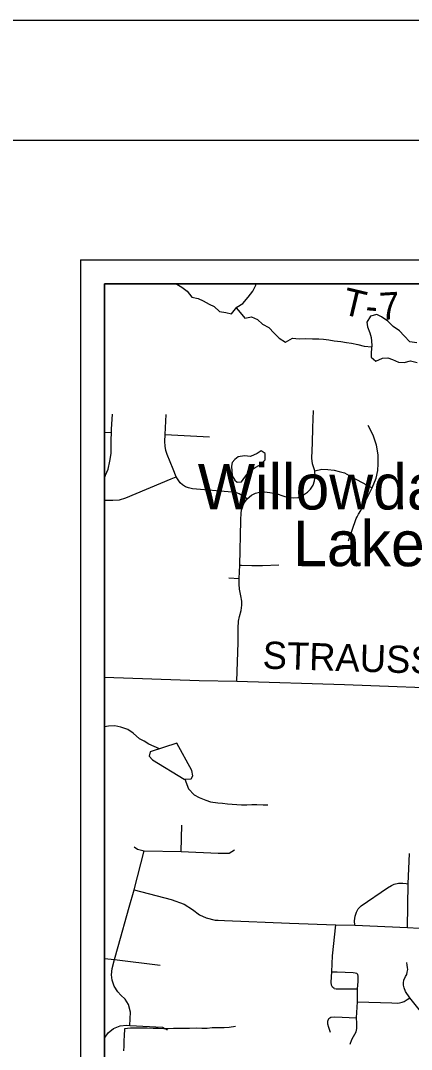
# Model space of a CAD drawing. Extents: x 25.6 to 80.6, y 0.2 to 24.5.
# Drawn here: x 37.263 to 38.894, y 17.932 to 22.23 of the extents above; entities that cross this region are included whole.
import ezdxf

# ---------------------------------------------------------------- set-up
doc = ezdxf.new("R2010")
doc.units = 0
for name, color, linetype in [('GM_X_County_Road', 7, 'Continuous'), ('GM_X_County_Road_Text', 7, 'Continuous'), ('GM_X_Minor_Lake', 7, 'Continuous'), ('GM_X_Minor_Lake_Text', 7, 'Continuous'), ('GM_X_Minor_River', 7, 'Continuous'), ('GM_X_Township_Road', 7, 'Continuous'), ('GM_X_Township_Road_Text', 7, 'Continuous'), ('SH_Border', 7, 'Continuous'), ('SH_Cut_Line', 7, 'Continuous'), ('SH_Data', 7, 'Continuous'), ('SH_Text', 7, 'Continuous')]:
    doc.layers.add(name, color=color, linetype=linetype)

msp = doc.modelspace()

# ---------------------------------------------------------------- linework, layer by layer
at = {"layer": 'GM_X_County_Road'}
msp.add_lwpolyline([(37.6128, 19.4872), (38.0081, 19.473), (38.1648, 19.4698), (38.614, 19.4559), (39.1271, 19.4367), (39.3128, 19.4303)], dxfattribs=at)
at = {"layer": 'GM_X_Minor_Lake'}
for points in [[(38.9165, 20.8834), (38.8877, 20.8884), (38.8631, 20.9124), (38.8439, 20.9342), (38.8179, 20.9514), (38.7956, 20.9747), (38.7689, 20.9926), (38.7498, 21.0022), (38.7233, 20.9958), (38.707, 20.9706), (38.7102, 20.9509), (38.7196, 20.9252), (38.7252, 20.9055), (38.7286, 20.8736), (38.7259, 20.8432), (38.7254, 20.8242), (38.7453, 20.807), (38.7732, 20.8202), (38.7952, 20.8213), (38.8142, 20.8147), (38.8394, 20.8028), (38.8637, 20.8023), (38.8894, 20.8087), (38.9175, 20.8022)], [(38.9165, 20.8834), (38.8877, 20.8884), (38.8631, 20.9124), (38.8439, 20.9342), (38.8179, 20.9514), (38.7956, 20.9747), (38.7689, 20.9926), (38.7498, 21.0022), (38.7233, 20.9958), (38.707, 20.9706), (38.7102, 20.9509), (38.7196, 20.9252), (38.7252, 20.9055), (38.7286, 20.8736), (38.7259, 20.8432), (38.7254, 20.8242), (38.7453, 20.807), (38.7732, 20.8202), (38.7952, 20.8213), (38.8142, 20.8147), (38.8394, 20.8028), (38.8637, 20.8023), (38.8894, 20.8087), (38.9175, 20.8022)], [(38.1452, 20.3285), (38.1561, 20.3096), (38.166, 20.3021), (38.1842, 20.3024), (38.1992, 20.3223), (38.2163, 20.346), (38.2419, 20.363), (38.26, 20.3723), (38.2832, 20.3946), (38.2829, 20.422), (38.2668, 20.4332), (38.2495, 20.4208), (38.2224, 20.4083), (38.1973, 20.4119), (38.1708, 20.407), (38.1573, 20.397), (38.1461, 20.3832), (38.1425, 20.3687)], [(38.1425, 20.3687), (38.1452, 20.3285)], [(37.9146, 19.2118), (37.8036, 19.1756), (37.7992, 19.1566), (37.8131, 19.1416), (37.946, 19.0603), (37.9748, 19.0622), (37.9815, 19.0752), (37.9774, 19.0964)], [(37.9774, 19.0964), (37.9146, 19.2118)]]:
    msp.add_lwpolyline(points, dxfattribs=at)
at = {"layer": 'GM_X_Minor_River'}
for points in [[(37.9128, 21.1303), (37.9149, 21.1284), (37.9355, 21.1165), (37.9585, 21.0993), (37.9777, 21.0752), (38.0036, 21.0695), (38.0242, 21.0591), (38.0494, 21.0449), (38.0699, 21.0361), (38.0922, 21.0151), (38.1188, 21.0108), (38.1423, 21.005), (38.1648, 21.0326), (38.1896, 21.0481), (38.212, 21.0742), (38.2322, 21.1002), (38.244, 21.1247), (38.2452, 21.1303)], [(38.1628, 21.0302), (38.1787, 21.01), (38.1987, 20.9867), (38.2267, 20.9931), (38.2511, 20.9812), (38.2718, 20.9617), (38.2993, 20.9484), (38.3215, 20.9236), (38.3415, 20.9033), (38.3682, 20.8869), (38.3969, 20.9032), (38.4257, 20.9005), (38.453, 20.9023), (38.4811, 20.9011), (38.5069, 20.8999), (38.5273, 20.8986), (38.5494, 20.8959), (38.5714, 20.8916), (38.5995, 20.8888), (38.6223, 20.8853), (38.6436, 20.8825), (38.6694, 20.8775), (38.696, 20.8702), (38.728, 20.867)], [(37.8418, 19.1881), (37.7986, 19.2074), (37.7788, 19.2194), (37.7589, 19.229), (37.7321, 19.253), (37.7099, 19.2687), (37.6817, 19.2782), (37.6567, 19.284), (37.6294, 19.2822), (37.6128, 19.28)], [(37.9475, 19.0604), (37.9639, 19.0203), (37.987, 18.9955), (38.0083, 18.9844), (38.0358, 18.9725), (38.0548, 18.9659), (38.0852, 18.9617), (38.1057, 18.9604), (38.1262, 18.9576), (38.1459, 18.9556), (38.1657, 18.9543), (38.1846, 18.9538), (38.2066, 18.9533), (38.2271, 18.955), (38.2483, 18.9545), (38.2749, 18.9533), (38.2938, 18.9528)], [(38.1595, 18.0271), (38.133, 18.023), (38.1125, 18.022), (38.0845, 18.0224), (38.0617, 18.0214), (38.0413, 18.0189), (38.0185, 18.0186), (37.9988, 18.0199), (37.967, 18.0188), (37.9465, 18.0193), (37.901, 18.0188), (37.879, 18.0177), (37.8601, 18.0175), (37.8365, 18.0188), (37.8153, 18.0185), (37.791, 18.0198), (37.7652, 18.0202), (37.7213, 18.0197), (37.6963, 18.0171), (37.6943, 17.989), (37.6938, 17.9685), (37.6941, 17.9457), (37.6928, 17.9252)]]:
    msp.add_lwpolyline(points, dxfattribs=at)
at = {"layer": 'GM_X_Township_Road'}
for p, q in [((37.6128, 20.5104), (37.6423, 20.5093)), ((37.8663, 20.5003), (38.0505, 20.4916)), ((38.1311, 19.9013), (38.1747, 19.899)), ((37.9328, 18.7581), (37.9352, 18.8679))]:
    msp.add_line(p, q, dxfattribs=at)
for points in [[(38.2076, 20.2323), (38.2262, 20.247), (38.2435, 20.2561), (38.2595, 20.2599), (38.2812, 20.2617), (38.3033, 20.2587), (38.3336, 20.253), (38.3569, 20.2448), (38.379, 20.2379), (38.4011, 20.2361), (38.4205, 20.2379), (38.4392, 20.2461), (38.4599, 20.2595), (38.472, 20.2721), (38.4833, 20.2889), (38.4889, 20.3071), (38.4915, 20.3249), (38.4902, 20.3495), (38.4811, 20.3777), (38.4777, 20.4015), (38.4807, 20.4664), (38.4829, 20.5287), (38.4846, 20.6005)], [(37.6423, 20.5093), (37.6428, 20.5226), (37.6468, 20.5854)], [(37.9151, 20.3195), (37.9118, 20.3246), (37.8988, 20.3559), (37.8743, 20.4167), (37.8687, 20.4346), (37.8657, 20.4524), (37.8651, 20.472), (37.8663, 20.5003), (37.87, 20.5839)], [(37.6128, 20.3182), (37.6174, 20.3313), (37.6276, 20.3563), (37.6352, 20.3896), (37.6403, 20.4221), (37.6413, 20.4772), (37.6423, 20.5093)], [(38.6314, 20.0561), (38.6631, 20.1501), (38.6669, 20.1574), (38.6701, 20.1626), (38.6735, 20.1681), (38.6828, 20.1838), (38.73, 20.2781), (38.7464, 20.3188), (38.7529, 20.35), (38.7555, 20.3777), (38.7551, 20.4153), (38.7482, 20.4556), (38.7352, 20.4937), (38.7257, 20.5149), (38.7131, 20.5382)], [(38.4902, 20.3495), (38.5205, 20.3556), (38.5448, 20.3552), (38.5707, 20.3517), (38.5924, 20.3469), (38.6144, 20.34), (38.6443, 20.324), (38.73, 20.2781)], [(37.6128, 20.2262), (37.6474, 20.2262), (37.6754, 20.2285), (37.7025, 20.2361), (37.8906, 20.3158), (37.9118, 20.3246)], [(38.2076, 20.2323), (38.1752, 20.253), (38.1609, 20.2582), (38.1453, 20.2595), (37.9806, 20.2742), (37.964, 20.2773), (37.9511, 20.2828), (37.9382, 20.2902), (37.9284, 20.2994), (37.9151, 20.3195)], [(38.1648, 19.4698), (38.17, 19.6324), (38.1704, 19.6917), (38.1717, 19.7211), (38.176, 19.741), (38.1834, 19.7661), (38.1864, 19.7874), (38.1855, 19.8042), (38.1821, 19.8272), (38.1756, 19.8544), (38.1747, 19.8748), (38.1747, 19.899), (38.1778, 19.9553), (38.1825, 20.1409), (38.1834, 20.1751), (38.1864, 20.1907), (38.1903, 20.2033), (38.1977, 20.2167), (38.2076, 20.2323)], [(38.1778, 19.9553), (38.1848, 19.9551), (38.2284, 19.954), (38.2717, 19.9535), (38.3409, 19.9561)], [(37.7188, 18.0322), (37.7214, 18.0875), (37.7129, 18.1197), (37.6991, 18.142), (37.6813, 18.1585), (37.6682, 18.1723), (37.6537, 18.1963), (37.6455, 18.2213), (37.6422, 18.243), (37.6451, 18.269), (37.6553, 18.3068), (37.6705, 18.362), (37.7155, 18.5261), (37.7361, 18.5978), (37.7788, 18.7613)], [(37.7361, 18.7787), (37.7511, 18.7684), (37.7788, 18.7613), (37.9328, 18.7581), (38.0876, 18.751), (38.1326, 18.7518), (38.1555, 18.7653)], [(38.8779, 18.4416), (38.8805, 18.6236), (38.886, 18.7505)], [(38.6581, 18.4508), (38.6559, 18.4692), (38.6594, 18.4883), (38.6644, 18.5048), (38.6715, 18.5183), (38.684, 18.5319), (38.7933, 18.6061), (38.8108, 18.6166), (38.8219, 18.6216), (38.8404, 18.6256), (38.8575, 18.6266), (38.8715, 18.6246), (38.8805, 18.6236)], [(37.7361, 18.5978), (37.8917, 18.5575), (37.9455, 18.5378), (37.9802, 18.5157), (38.0094, 18.4936), (38.0378, 18.4809), (38.075, 18.4722), (38.0872, 18.4715)], [(38.0872, 18.4715), (38.1137, 18.4699), (38.3845, 18.4588), (38.5779, 18.4524), (38.6581, 18.4508), (38.8779, 18.4416), (39.1211, 18.4267)], [(38.5713, 18.1862), (38.5638, 18.1922), (38.56, 18.2), (38.5592, 18.212), (38.5622, 18.2555), (38.5638, 18.3219), (38.5779, 18.4524)], [(37.6128, 18.311), (37.6553, 18.3068), (37.8457, 18.2834)], [(39.1098, 18.0552), (39.0148, 18.0575), (38.9845, 18.0586), (38.9645, 18.0634), (38.9504, 18.071), (38.932, 18.0916), (38.8872, 18.1478), (38.8696, 18.174), (38.8631, 18.1892), (38.8603, 18.2), (38.8603, 18.2092), (38.8625, 18.2206), (38.869, 18.2363), (38.8739, 18.2444), (38.8766, 18.2547), (38.8782, 18.265), (38.8777, 18.2742), (38.8766, 18.2834), (38.8744, 18.2954)], [(38.5622, 18.2555), (38.5836, 18.2564), (38.651, 18.2528), (38.6583, 18.252), (38.664, 18.2499), (38.6694, 18.245)], [(38.6386, 17.9536), (38.6457, 17.9725), (38.6522, 17.986), (38.6625, 18.0055), (38.6657, 18.0191), (38.6657, 18.0412), (38.6646, 18.0633), (38.6686, 18.1307), (38.6683, 18.1849), (38.6711, 18.216), (38.6719, 18.2293), (38.6719, 18.2379), (38.6694, 18.245)], [(38.5713, 18.1862), (38.5803, 18.1843), (38.6228, 18.1851), (38.6451, 18.1854), (38.6683, 18.1849)], [(38.6686, 18.1307), (38.8121, 18.1258), (38.8341, 18.125), (38.8446, 18.1258), (38.8547, 18.1285), (38.8628, 18.1318), (38.8766, 18.1396), (38.8872, 18.1478)], [(38.5564, 18.0028), (38.5488, 18.0228), (38.5455, 18.0364), (38.5455, 18.0499), (38.5488, 18.0602), (38.5575, 18.0667), (38.5742, 18.0678), (38.6646, 18.0633)], [(37.6128, 17.9779), (37.6129, 17.9783), (37.6287, 18.0013), (37.6498, 18.0184), (37.678, 18.0296), (37.705, 18.0329), (37.7188, 18.0322), (37.8556, 18.0243), (37.8747, 18.0132)]]:
    msp.add_lwpolyline(points, dxfattribs=at)
at = {"layer": 'SH_Border'}
msp.add_lwpolyline([(37.0128, 21.7303), (69.0128, 21.7303), (69.0128, 0.7303), (37.0128, 0.7303)], close=True, dxfattribs=at)
at = {"layer": 'SH_Cut_Line'}
msp.add_lwpolyline([(35.5128, 0.2303), (69.5128, 0.2303), (69.5128, 22.2303), (35.5128, 22.2303)], close=True, dxfattribs=at)
at = {"layer": 'SH_Data'}
for p, q in [((37.5128, 21.2303), (44.5128, 21.2303)), ((37.5128, 21.2303), (37.5128, 14.2303)), ((37.6128, 21.1303), (37.6128, 14.3303)), ((37.6128, 21.1303), (44.4128, 21.1303)), ((37.6128, 21.1303), (37.6128, 14.3303)), ((37.6128, 21.1303), (44.4128, 21.1303))]:
    msp.add_line(p, q, dxfattribs=at)
at = {"layer": 'SH_Text'}
for points in [[(37.6128, 21.1303), (44.4128, 21.1303), (44.4128, 14.3303), (37.6128, 14.3303)], [(37.6128, 21.1303), (44.4128, 21.1303), (44.4128, 14.3303), (37.6128, 14.3303)], [(37.6128, 17.7303), (41.0128, 17.7303), (41.0128, 21.1303), (37.6128, 21.1303)], [(37.6128, 17.7303), (41.0128, 17.7303), (41.0128, 21.1303), (37.6128, 21.1303)]]:
    msp.add_lwpolyline(points, close=True, dxfattribs=at)

# ---------------------------------------------------------------- texts
at = {"layer": 'GM_X_County_Road_Text'}
msp.add_text('STRAUSSER ST', height=0.113636, rotation=358.1798, dxfattribs=at).set_placement((38.2715, 19.5229))
at = {"layer": 'GM_X_Minor_Lake_Text'}
for s, rotation, p in [('Willowdale', 359.9766, (38.0021, 20.1878)), ('Lake', 359.9767, (38.3999, 19.9507))]:
    msp.add_text(s, height=0.18945, rotation=rotation, dxfattribs=at).set_placement(p)
at = {"layer": 'GM_X_Township_Road_Text'}
for s, rotation, p in [('T', 346.6238, (38.598, 21.0056)), ('7', 3.6013, (38.7631, 20.979)), ('-', 355.2308, (38.6987, 20.983))]:
    msp.add_text(s, height=0.1136, rotation=rotation, dxfattribs=at).set_placement(p)

doc.saveas('drawing.dxf')
